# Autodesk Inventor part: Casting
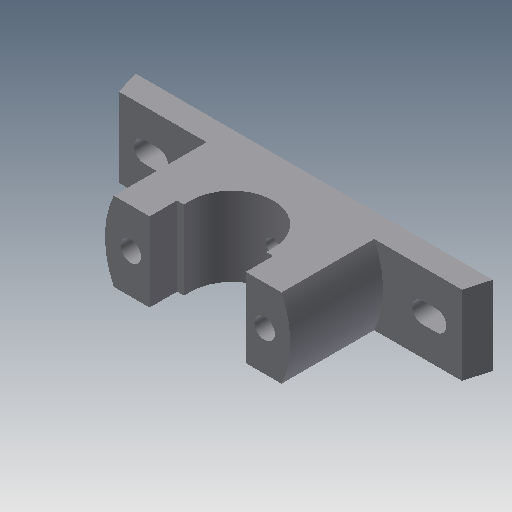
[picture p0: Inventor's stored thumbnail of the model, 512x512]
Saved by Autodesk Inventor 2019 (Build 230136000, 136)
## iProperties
Created: 2009-04
Part Number: Casting
Document SubType Name: Modeling
Designer: Sham
Density: 1 g/cm^3
Material: Generic
Appearance: Default
Author: Sham
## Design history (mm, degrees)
sketch "Sketch1"
  geometry: L1 (-104, 0)-(104, 0); L2 (-104, 0)-(-100, 14); L3 (-100, 14)-(100, 14); L4 (100, 14)-(104, 0); 1 further point
  constraints: 8 end point, 1 horizontal, 1 midpoint, 1 parallel, 1 other
  dimensions: "d0" = 208 distance of L1.start L1.end; "d1" = 104 distance of L1.end point (0, 0); "d2" = 4 horizontal distance of L1.start L2.end; "d3" = 4 horizontal distance of L1.end L3.end; "d10" = 14 distance between parallel lines of L1 L3
extrude "Extrusion1" new body sketch "Sketch1" stored distance "d4" = 46; taper "d5" = 0 deg
sketch "Sketch2"
  geometry: L1 (51.143, 46)-(148.857, 46); L2 (148.857, 0)-(51.143, 0); A1 r 54 centre (100, 23) between (51.143, 46) and (51.143, 0); A2 r 54 centre (100, 23) between (148.857, 0) and (148.857, 46)
  constraints: 4 end point, 4 point on circle, 2 centre point, 1 parallel
extrude "Extrusion2" join sketch "Sketch2" distance "d8" = 54; taper "d9" = 0 deg
sketch "Sketch3"
  geometry: L1 (-28, 68)-(-28, 52); L2 (-28, 52)-(-24, 52); L3 (28, 68)-(28, 52); L4 (28, 52)-(24, 52); L5 (-28, 68)-(28, 68); L6 (-100, 14)-(-48.857, 14) reference; L7 (0, 48)-(0, 19); L8 (48.857, 14)-(100, 14) reference; L9 (48.857, 68)-(-48.857, 68) reference; L10 (-24, 48)-(-24, 52); L11 (24, 48)-(24, 52); A1 r 24 centre (0, 48) between (-24, 48) and (24, 48); 1 further point
  constraints: 16 end point, 5 perpendicular, 2 point on circle, 2 symmetric about line, 1 centre point, 1 tangent, 1 vertical alignment, 1 other
  dimensions: "d11" = 16 distance of L1.start L1.end; "d16" = 24 radius of A1; "d17" = 16 distance of L3.start L3.end; "d52" = 56 distance between parallel lines of L1 L3; "d54" = 54 distance between parallel lines of L8 L9 (derived)
extrude "Extrusion3" cut sketch "Sketch3" distance "d18" = 54; taper "d19" = 0 deg
sketch "Sketch4"
  geometry: L1 (-23, 29)-(-15, 29); L2 (-15, 17)-(-23, 17); L3 (-185, 29)-(-177, 29); L4 (-177, 17)-(-185, 17); A1 r 6 centre (-15, 23) between (-15, 17) and (-15, 29); A2 r 6 centre (-23, 23) between (-23, 29) and (-23, 17); A3 r 6 centre (-177, 23) between (-177, 17) and (-177, 29); A4 r 6 centre (-185, 23) between (-185, 29) and (-185, 17)
  constraints: 8 end point, 8 point on circle, 8 tangent, 4 centre point, 3 parallel
  dimensions: "d20" = 8 distance of A1.centre A2.centre; "d21" = 6 radius of A1; "d24" = 6 radius of A3; "d25" = 8 distance of A4.centre A3.centre
extrude "Extrusion4" cut sketch "Sketch4" distance "d28" = 54; taper "d29" = 0 deg
sketch "Sketch5"
  geometry: L1 (208, 0)-(0, 0) reference; L2 (52, -10)-(78, -10); L3 (78, -10)-(78, -36); L4 (78, -36)-(52, -36); L5 (52, -36)-(52, -10); L6 (130, -10)-(156, -10); L7 (156, -10)-(156, -36); L8 (156, -36)-(130, -36); L9 (130, -36)-(130, -10); L10 (0, -46)-(208, -46) reference; L11 (104, -23)-(104, -46)
  constraints: 18 end point, 5 perpendicular, 4 parallel, 2 horizontal, 1 midpoint
  dimensions: "d30" = 26 distance of L2.start L2.end; "d31" = 10 distance between parallel lines of L2 L1; "d32" = 10 distance between parallel lines of L1 L6; "d65" = 26 distance between parallel lines of L3 L11; "d66" = 26 distance between parallel lines of L9 L11
extrude "Extrusion5" cut sketch "Sketch5" distance "d34" = 10; taper "d35" = 0 deg
sketch "Sketch6"
  geometry: L1 (148.857, 0)-(128, 0) reference; L2 (72, 0)-(51.143, 0) reference; L3 (0, 46)-(0, 0) reference; L4 (200, 46)-(200, 0) reference; C1 r 6 at (61, 23); C2 r 6 at (139, 23); 1 further point
  constraints: 2 centre point, 1 equal radius
  dimensions: "d36" = 12 diameter of C1; "d37" = 78 distance of C2.centre C1.centre; "d39" = 39 distance of C2.centre point (100, 23); "d58" = 39 distance of C1.centre point (100, 23); "d59" = 23 distance from line of L1 C2.centre; "d60" = 23 distance from line of L2 C1.centre; "d61" = 61 distance from line of L3 C1.centre; "d62" = 61 distance from line of L4 C2.centre (derived)
extrude "Extrusion6" cut sketch "Sketch6" extent not by distance; stored distance "d40" = 10; taper "d41" = 0 deg
workplane "Work Plane1"
sketch "Sketch7"
  geometry: L1 (-4, 46)-(204, 46) reference; L2 (-4, 0)-(-4, 46) reference; 1 further point
  dimensions: "d43" = 23 distance from line of L1 point (100, 23); "d44" = 104 distance from line of point (100, 23) L2
hole "Hole1" sketch "Sketch7" at (100, 23) diameter "d45" = 8; stored, may be unused: countersink angle "d49" = 90 deg, drill point angle "d51" = 118 deg; dims "d46" = 6, "d47" = 8, "d48" = 16, "d50" = 8
body "Solid1"
other parameters: "d6" = 108, "d42" = -52
